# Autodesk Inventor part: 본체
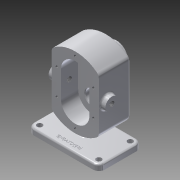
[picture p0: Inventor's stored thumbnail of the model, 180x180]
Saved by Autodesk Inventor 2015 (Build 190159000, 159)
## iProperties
Created: 2019-03
Part Number: 본체
Material: 알루미늄 6061
Document SubType Name: Modeling
Designer: now
Density: 2.7 g/cm^3
Appearance: 알루미늄 - 평지
Mass: 1186.71 g
Surface Area: 720.452 cm^2
Volume: 439.521 cm^3
Author: now
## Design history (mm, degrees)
sketch "스케치1"
  geometry: L1 (-60, 36.5)-(60, 36.5); L2 (60, 36.5)-(60, -36.5); L3 (60, -36.5)-(-60, -36.5); L4 (-60, -36.5)-(-60, 36.5); L5 (-60, 36.5)-(60, -36.5); L6 (60, 36.5)-(-60, -36.5); 1 further point
  constraints: 12 end point, 2 midpoint, 2 parallel, 1 horizontal, 1 perpendicular
  dimensions: "d0" = 120 distance of L2.end L3.end; "d1" = 73 distance of L1.end L2.end
extrude "돌출1" new body sketch "스케치1" distance "d2" = 10; taper "d3" = 0 deg
fillet "모깎기1" dims "d4" = 10
sketch "스케치2"
  geometry: L1 (-60, -26.5)-(-60, 26.5) reference; L2 (-50, 36.5)-(50, 36.5) reference; L3 (60, 26.5)-(60, -26.5) reference; L4 (50, -36.5)-(-50, -36.5) reference; L5 (-6, 36.5)-(6, 36.5); L6 (6, 36.5)-(6, -6.5); L7 (6, -6.5)-(-6, -6.5); L8 (-6, -6.5)-(-6, 36.5); A1 r 10 centre (-50, -26.5) between (-60, -26.5) and (-50, -36.5) reference; A2 r 10 centre (-50, 26.5) between (-50, 36.5) and (-60, 26.5) reference; A3 r 10 centre (50, 26.5) between (60, 26.5) and (50, 36.5) reference; A4 r 10 centre (50, -26.5) between (50, -36.5) and (60, -26.5) reference; 2 further points
  constraints: 8 end point, 2 parallel, 1 horizontal, 1 midpoint, 1 perpendicular, 1 point on line, 1 vertical alignment
  dimensions: "d5" = 12 distance of L6.end L7.end; "d6" = 43 distance of L5.end L6.end
extrude "돌출2" join sketch "스케치2" distance "d7" = 68; taper "d8" = 0 deg
sketch "스케치3"
  geometry: L1 (60, 0)-(-60, 0) reference; L2 (-60, 0)-(-60, 10) reference; L3 (-60, 10)-(-6, 10) reference; L4 (-6, 10)-(-6, 78) reference; L5 (-6, 78)-(6, 78) reference; L6 (6, 78)-(6, 10) reference; L7 (6, 10)-(60, 10) reference; L8 (60, 10)-(60, 0) reference; L9 (40, 122.721)-(40, 33.279); L10 (-40, 122.721)-(-40, 33.279); L11 (0, 138)-(0, 18); A1 r 60 centre (0, 78) between (-40, 33.279) and (40, 33.279); A2 r 60 centre (0, 78) between (40, 122.721) and (-40, 122.721); 2 further points
  constraints: 6 end point, 6 point on circle, 2 centre point, 2 midpoint, 2 vertical, 1 coincident, 1 parallel, 1 other
  dimensions: "d13" = 80 distance between parallel lines of L10 L9; "d14" = 60 radius of A2
extrude "돌출3" join sketch "스케치3" distance "d15" = 36.5; taper "d17" = 0 deg; dims "d16" = 16.5, "d18" = 0
fillet "모깎기2" dims "d19" = 10
sketch "스케치4"
  geometry: L1 (-40, 38)-(-40, 118) reference; L2 (40, 118)-(40, 38) reference; L3 (60, 0)-(-60, 0) reference; L4 (-60, 0)-(-60, 10) reference; L5 (-60, 10)-(60, 10) reference; L6 (60, 10)-(60, 0) reference; L7 (-24, 100)-(-24, 56); L8 (24, 100)-(24, 56); L9 (40, 118)-(40, 38) reference; A1 r 24 centre (0, 100) between (24, 100) and (-24, 100); A2 r 24 centre (0, 56) between (-24, 56) and (24, 56); A3 r 10 centre (30, 38) between (36, 30) and (40, 38) reference; A4 r 60 centre (0, 78) between (-36, 30) and (36, 30) reference; A5 r 10 centre (-30, 38) between (-40, 38) and (-36, 30) reference; A6 r 10 centre (-30, 118) between (-36, 126) and (-40, 118) reference; A7 r 60 centre (0, 78) between (36, 126) and (-36, 126) reference; A8 r 10 centre (30, 118) between (40, 118) and (36, 126) reference; 2 further points
  constraints: 4 end point, 4 point on circle, 3 vertical alignment, 2 centre point, 2 tangent, 2 vertical, 1 horizontal alignment, 1 midpoint
  dimensions: "d20" = 48 diameter of A1; "d21" = 48 diameter of A2; "d22" = 44 distance of L8.start L8.end
extrude "돌출4" cut sketch "스케치4" distance "d23" = 29; taper "d24" = 0 deg
sketch "스케치5"
  geometry: L1 (-24, 100)-(-24, 56) reference; L2 (24, 56)-(24, 100) reference; L3 (60, 0)-(-60, 0) reference; L4 (-60, 0)-(-60, 10) reference; L5 (-60, 10)-(-6, 10) reference; L6 (-6, 10)-(-6, 18.301) reference; L7 (-40, 38)-(-40, 118) reference; L8 (40, 118)-(40, 38) reference; L9 (6, 18.301)-(6, 10) reference; L10 (6, 10)-(60, 10) reference; L11 (60, 10)-(60, 0) reference; A1 r 24 centre (0, 56) between (-24, 56) and (24, 56) reference; A2 r 24 centre (0, 100) between (24, 100) and (-24, 100) reference; A3 r 60 centre (0, 78) between (-36, 30) and (-6, 18.301) reference; A4 r 10 centre (-30, 38) between (-40, 38) and (-36, 30) reference; A5 r 10 centre (-30, 118) between (-36, 126) and (-40, 118) reference; A6 r 60 centre (0, 78) between (36, 126) and (-36, 126) reference; A7 r 10 centre (30, 118) between (40, 118) and (36, 126) reference; A8 r 10 centre (30, 38) between (36, 30) and (40, 38) reference; A9 r 60 centre (0, 78) between (6, 18.301) and (36, 30) reference; 1 further point
hole "구멍1" sketch "스케치5" at (0, 56) diameter "d25" = 25; stored, may be unused: countersink angle "d29" = 90 deg, drill point angle "d31" = 0 deg; dims "d26" = 6, "d27" = 4, "d28" = 2, "d30" = 15
sketch "스케치6"
  geometry: L1 (40, -38)-(40, -118) reference; L2 (-40, -118)-(-40, -38) reference; L3 (24, -100)-(24, -56) reference; L4 (-24, -56)-(-24, -100) reference; L5 (-6, -18.301)-(-6, -10) reference; L6 (-6, -10)-(-50, -10) reference; L7 (-50, 0)-(-50, -10) reference; L8 (-50, 0)-(50, 0) reference; L9 (50, 0)-(50, -10) reference; L10 (50, -10)-(6, -10) reference; L11 (6, -10)-(6, -18.301) reference; C1 r 12.5 at (0, -56) reference; C2 r 19 at (0, -100); A1 r 10 centre (30, -38) between (40, -38) and (36, -30) reference; A2 r 10 centre (30, -118) between (36, -126) and (40, -118) reference; A3 r 60 centre (0, -78) between (-36, -126) and (36, -126) reference; A4 r 10 centre (-30, -118) between (-40, -118) and (-36, -126) reference; A5 r 10 centre (-30, -38) between (-36, -30) and (-40, -38) reference; A6 r 24 centre (0, -100) between (-24, -100) and (24, -100) reference; A7 r 24 centre (0, -56) between (24, -56) and (-24, -56) reference; A8 r 60 centre (0, -78) between (-6, -18.301) and (-36, -30) reference; A9 r 60 centre (0, -78) between (36, -30) and (6, -18.301) reference; 1 further point
  constraints: 1 centre point, 1 coincident
  dimensions: "d33" = 38 diameter of C2
extrude "돌출5" join sketch "스케치6" distance "d34" = 17; taper "d35" = 0 deg
sketch "스케치7"
  geometry: C1 r 19 at (0, 0) reference; 1 further point
hole "구멍2" sketch "스케치7" at (0, 0) diameter "d36" = 17; stored, may be unused: countersink angle "d40" = 90 deg, drill point angle "d42" = 0 deg; dims "d37" = 6, "d38" = 28, "d39" = 7.3, "d41" = 15
sketch "스케치8"
  geometry: L1 (-24, 100)-(-24, 56) reference; L2 (24, 56)-(24, 100) reference; L3 (60, 0)-(-60, 0) reference; L4 (-60, 0)-(-60, 10) reference; L5 (-60, 10)-(-6, 10) reference; L6 (-6, 10)-(-6, 18.301) reference; L7 (-40, 38)-(-40, 118) reference; L8 (40, 118)-(40, 38) reference; L9 (6, 18.301)-(6, 10) reference; L10 (6, 10)-(60, 10) reference; L11 (60, 10)-(60, 0) reference; C1 r 8.5 at (0, 100) reference; C2 r 12.5 at (0, 56) reference; A1 r 24 centre (0, 56) between (-24, 56) and (24, 56) reference; A2 r 24 centre (0, 100) between (24, 100) and (-24, 100) reference; A3 r 60 centre (0, 78) between (-36, 30) and (-6, 18.301) reference; A4 r 10 centre (-30, 38) between (-40, 38) and (-36, 30) reference; A5 r 10 centre (-30, 118) between (-36, 126) and (-40, 118) reference; A6 r 60 centre (0, 78) between (36, 126) and (-36, 126) reference; A7 r 10 centre (30, 118) between (40, 118) and (36, 126) reference; A8 r 10 centre (30, 38) between (36, 30) and (40, 38) reference; A9 r 60 centre (0, 78) between (6, 18.301) and (36, 30) reference; 1 further point
hole "구멍3" sketch "스케치8" at (0, 100) diameter "d43" = 17; stored, may be unused: countersink angle "d47" = 90 deg, drill point angle "d49" = 0 deg; dims "d44" = 6, "d45" = 25, "d46" = 15, "d48" = 15
sketch "스케치9"
  geometry: L1 (-60, -26.5)-(-60, 26.5) reference; L2 (-50, 36.5)-(-6, 36.5) reference; L3 (-6, -6.5)-(-6, 36.5) reference; L4 (6, -6.5)-(-6, -6.5) reference; L5 (6, 36.5)-(6, -6.5) reference; L6 (-6, 36.5)-(6, 36.5) reference; L7 (50, -36.5)-(-50, -36.5) reference; L8 (60, 26.5)-(60, -26.5) reference; L9 (6, 36.5)-(50, 36.5) reference; A1 r 10 centre (-50, -26.5) between (-60, -26.5) and (-50, -36.5) reference; A2 r 10 centre (-50, 26.5) between (-50, 36.5) and (-60, 26.5) reference; A3 r 10 centre (50, -26.5) between (50, -36.5) and (60, -26.5) reference; A4 r 10 centre (50, 26.5) between (60, 26.5) and (50, 36.5) reference; 1 further point
hole "구멍4" sketch "스케치9" at (-50, -26.5), (50, -26.5), (50, 26.5), (-50, 26.5) diameter "d50" = 9; stored, may be unused: countersink angle "d54" = 90 deg, drill point angle "d56" = 0 deg; dims "d51" = 6, "d52" = 25, "d53" = 15, "d55" = 15
sketch "스케치10"
  geometry: L1 (0, 0)-(-80, 0) reference; L2 (-80, 53)-(-80, 0) reference; L3 (-80, 53)-(0, 53) reference; L4 (0, 53)-(0, 0) reference; L5 (28, 53)-(38, 53) reference; L6 (38, 53)-(38, -20) reference; L7 (38, -20)-(28, -20) reference; L8 (28, -20)-(28, 53) reference; C1 r 11 at (-40, 14); 2 further points
  constraints: 1 centre point, 1 midpoint, 1 vertical alignment
  dimensions: "d60" = 22 diameter of C1; "d61" = 14 distance from line of C1.centre L1
extrude "돌출6" join sketch "스케치10" distance "d58" = 8; taper "d59" = 0 deg
sketch "스케치11"
  geometry: L1 (78, -19.969)-(68, -19.969) reference; L2 (68, -19.969)-(68, 24.969) reference; L3 (68, 24.969)-(78, 24.969) reference; L4 (78, 24.969)-(78, -19.969) reference; L5 (68, -28.031)-(78, -28.031) reference; L6 (78, -28.031)-(78, -34) reference; L7 (78, -34)-(68, -34) reference; L8 (68, -34)-(68, -28.031) reference; L9 (68, 39)-(78, 39) reference; L10 (78, 39)-(78, 33.031) reference; L11 (78, 33.031)-(68, 33.031) reference; L12 (68, 33.031)-(68, 39) reference; C1 r 11 at (0, 0) reference; 1 further point
hole "구멍5" sketch "스케치11" at (0, 0) diameter "d62" = 8.376; stored, may be unused: countersink angle "d66" = 90 deg, drill point angle "d68" = 0 deg; dims "d63" = 20, "d64" = 25, "d65" = 15, "d67" = 27.3
sketch "스케치12"
  geometry: L1 (-24, 100)-(-24, 56) reference; L2 (24, 56)-(24, 100) reference; L3 (-40, 38)-(-40, 118) reference; L4 (40, 118)-(40, 38) reference; L5 (60, 0)-(-60, 0) reference; L6 (-60, 0)-(-60, 10) reference; L7 (-60, 10)-(60, 10) reference; L8 (60, 10)-(60, 0) reference; L9 (-31, 100)-(31, 100); L10 (-31, 56)-(31, 56); L11 (0, 131)-(0, 25); A1 r 24 centre (0, 56) between (-24, 56) and (24, 56) reference; A2 r 24 centre (0, 100) between (24, 100) and (-24, 100) reference; A3 r 10 centre (30, 38) between (36, 30) and (40, 38) reference; A4 r 60 centre (0, 78) between (-36, 30) and (36, 30) reference; A5 r 10 centre (-30, 38) between (-40, 38) and (-36, 30) reference; A6 r 10 centre (-30, 118) between (-36, 126) and (-40, 118) reference; A7 r 60 centre (0, 78) between (36, 126) and (-36, 126) reference; A8 r 10 centre (30, 118) between (40, 118) and (36, 126) reference; 5 further points
  constraints: 6 end point, 3 coincident, 3 midpoint, 2 horizontal, 1 vertical
  dimensions: "d71" = 62 distance of L10.start L10.end; "d72" = 62 distance of L9.start L9.end; "d73" = 31 distance from line of L9 L11.start
hole "구멍6" sketch "스케치12" at (0, 131), (-31, 100), (-31, 56), (0, 25), (31, 56), (31, 100) diameter "d74" = 4.134; stored, may be unused: countersink angle "d78" = 90 deg, drill point angle "d80" = 118 deg; dims "d75" = 10, "d76" = 25, "d77" = 15, "d79" = 12
fillet "모깎기3" dims "d81" = 3
fillet "모깎기5" dims "d83" = 3
fillet "모깎기6" dims "d84" = 3
chamfer "모따기1" distance "d85" = 1; stored, may be unused: second distance "d86" = 2, angle "d87" = 45 deg
fillet "모깎기9" dims "d90" = 3
sketch "스케치13"
  geometry: L1 (-6, 33.5)-(-50, 33.5) reference; L2 (-57, 26.5)-(-57, -26.5) reference; L3 (-50, -33.5)-(50, -33.5) reference; L4 (57, -26.5)-(57, 26.5) reference; L5 (50, 33.5)-(6, 33.5) reference; L6 (50, -36.5)-(-50, -36.5) reference; L7 (-60, 26.5)-(-60, -26.5) reference; L8 (6, 33.5)-(6, -6.5) reference; L9 (-6, -6.5)-(-6, 33.5) reference; L10 (-6, 36.5)-(6, 36.5) reference; L11 (6, 36.5)-(6, 33.5) reference; L12 (6, -6.5)-(-6, -6.5) reference; L13 (-6, 33.5)-(-6, 36.5) reference; C1 r 4.5 at (50, 26.5) reference; C2 r 4.5 at (-50, -26.5) reference; C3 r 4.5 at (50, -26.5) reference; C4 r 4.5 at (-50, 26.5) reference; A1 r 7 centre (-50, 26.5) between (-50, 33.5) and (-57, 26.5) reference; A2 r 7 centre (-50, -26.5) between (-57, -26.5) and (-50, -33.5) reference; A3 r 7 centre (50, -26.5) between (50, -33.5) and (57, -26.5) reference; A4 r 7 centre (50, 26.5) between (57, 26.5) and (50, 33.5) reference; 2 further points
  constraints: 1 other
  dimensions: "d91" = 10 distance from line of point (0, -26.5) L6; "d92" = 60 distance from line of point (0, -26.5) L7
feature "엠보싱1" sketch "스케치13" dims "d0" = 120, "d1" = 73, "d93" = 0.5, "d94" = 0
fillet "모깎기10" dims "d95" = 3
fillet "모깎기11" dims "d96" = 3
fillet "모깎기12" dims "d97" = 0.5
chamfer "모따기2" distance "d98" = 0.7; stored, may be unused: second distance "d99" = 2, angle "d100" = 30 deg
node "솔리드1"
mirror "대칭1"
node "투영된 루프1"
node "절단 모서리 투영1"
node "절단 모서리 투영2"
node "절단 모서리 투영3"
node "절단 모서리 투영4"
node "절단 모서리 투영5"
node "절단 모서리 투영6"
node "절단 모서리 투영7"
node "절단 모서리 투영8"
node "절단 모서리 투영9"
node "절단 모서리 투영10"
node "절단 모서리 투영11"
node "절단 모서리 투영12"
